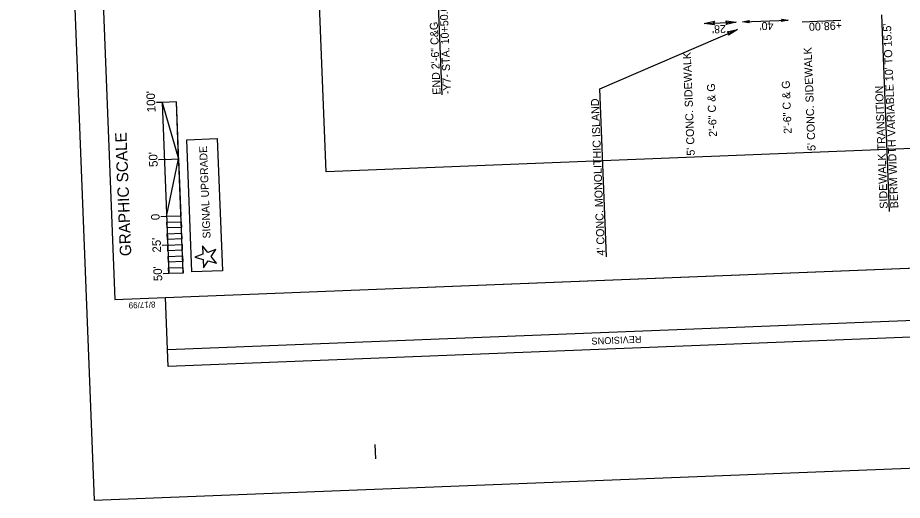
# Model space of a CAD drawing. Extents: x 1627811 to 1628977, y 762656 to 764629.
# Drawn here: x 1627811 to 1628584, y 762656 to 763078 of the extents above; entities that cross this region are included whole.
import ezdxf

# ---------------------------------------------------------------- set-up
doc = ezdxf.new("R2010")
doc.units = 0
for name, color, linetype in [('Prop Dimension', 7, 'Continuous'), ('Prop Dimension Text', 7, 'Continuous'), ('Prop DSN Text', 7, 'Continuous'), ('Prop Grid Mask', 7, 'Continuous'), ('Prop RDY Traffic Signal CELL', 7, 'Continuous'), ('Prop Terminator CELL', 7, 'Continuous'), ('Sheet Block Revision CELL', 7, 'Continuous'), ('Sheet Clip Boundary CELL', 7, 'Continuous'), ('Sheet Data Field CELL', 7, 'Continuous'), ('Sheet Plan And Profile CELL', 7, 'Continuous'), ('Sheet Plot Border Outside CELL', 7, 'Continuous'), ('Sheet Title CELL', 7, 'Continuous')]:
    doc.layers.add(name, color=color, linetype=linetype)

msp = doc.modelspace()

# ---------------------------------------------------------------- linework, layer by layer
at = {"layer": 'Prop Dimension'}
for p, q in [((1628181.73, 763010.81), (1628177.51, 763117.78)), ((1628573.2, 762908.58), (1628566.4, 763080.81)), ((1628411.15, 763073.24), (1628439.13, 763074.34)), ((1628444.62, 763074.56), (1628484.59, 763076.14)), ((1628496.92, 763074.62), (1628530.63, 763075.95)), ((1628319.92, 763015.96), (1628440.13, 763067.98)), ((1628325.72, 762868.94), (1628319.92, 763015.96))]:
    msp.add_line(p, q, dxfattribs=at)
at = {"layer": 'Prop Grid Mask'}
msp.add_lwpolyline([(1627962.94, 762855.84), (1627958.38, 762971.36), (1627985.14, 762972.42), (1627989.69, 762856.89)], close=True, dxfattribs=at)
at = {"layer": 'Prop RDY Traffic Signal CELL'}
msp.add_lwpolyline([(1627972.76, 762866.71), (1627973.05, 762859.31), (1627977.16, 762865.47), (1627984.31, 762863.46), (1627979.71, 762869.28), (1627983.83, 762875.45), (1627976.87, 762872.88), (1627972.28, 762878.7), (1627972.57, 762871.3), (1627965.61, 762868.72), (1627972.76, 762866.71)], dxfattribs=at)
at = {"layer": 'Prop Terminator CELL'}
for points in [[(1628420.2, 763072.04), (1628411.15, 763073.24), (1628420.13, 763075.19), (1628419.04, 763073.55)], [(1628430.07, 763075.54), (1628439.13, 763074.34), (1628430.15, 763072.39), (1628431.23, 763074.03)], [(1628450.5, 763073.73), (1628444.62, 763074.56), (1628450.47, 763075.78), (1628449.76, 763074.71)], [(1628478.72, 763076.97), (1628484.59, 763076.14), (1628478.74, 763074.92), (1628479.46, 763075.98)], [(1628431.25, 763065.83), (1628440.13, 763067.98), (1628432.46, 763062.92), (1628432.88, 763064.84)]]:
    msp.add_lwpolyline(points, close=True, dxfattribs=at)
at = {"layer": 'Sheet Block Revision CELL'}
msp.add_line((1628731.74, 762818.75), (1627941.71, 762787.59), dxfattribs=at)
msp.add_lwpolyline([(1628732.32, 762804.21), (1627942.28, 762773.06), (1627939.89, 762833.56), (1628729.93, 762864.71)], close=True, dxfattribs=at)
at = {"layer": 'Sheet Clip Boundary CELL'}
msp.add_lwpolyline([(1628080.25, 762943.5), (1628060.66, 763440.11), (1628567.89, 763460.11), (1628623.39, 763582.83), (1628623.86, 763610.17), (1628631.44, 763609.98), (1628639.19, 763612.32), (1628786.08, 763468.72), (1628805.66, 762972.11)], close=True, dxfattribs=at)
at = {"layer": 'Sheet Data Field CELL'}
for p, q in [((1627936.85, 763004.13), (1627931.85, 763003.94)), ((1627938.82, 762954.19), (1627933.83, 762953.99))]:
    msp.add_line(p, q, dxfattribs=at)
at = {"layer": 'Sheet Plan And Profile CELL'}
msp.add_line((1628123.76, 762692.19), (1628123.26, 762704.68), dxfattribs=at)
msp.add_lwpolyline([(1627836.47, 764330.65), (1627895.58, 762831.81), (1628944.76, 762873.18), (1628885.66, 764372.02)], close=True, dxfattribs=at)
at = {"layer": 'Sheet Plot Border Outside CELL'}
msp.add_lwpolyline([(1628976.64, 762699.3), (1628909.65, 764397.98), (1627810.51, 764354.64), (1627877.49, 762655.96)], close=True, dxfattribs=at)
at = {"layer": 'Sheet Title CELL'}
for p, q in [((1627936.85, 763004.12), (1627931.86, 763003.92)), ((1627949.35, 763004.62), (1627936.85, 763004.12)), ((1627936.85, 763004.12), (1627942.78, 762854.28)), ((1627955.26, 762854.78), (1627949.35, 763004.62)), ((1627938.83, 762954.18), (1627933.85, 762953.98)), ((1627938.83, 762954.18), (1627951.32, 762954.67)), ((1627940.81, 762904.23), (1627935.82, 762904.03)), ((1627941.8, 762879.26), (1627936.79, 762879.06)), ((1627942.78, 762854.28), (1627937.79, 762854.09))]:
    msp.add_line(p, q, dxfattribs=at)
for points in [[(1627936.85, 763004.12), (1627951.32, 762954.67), (1627949.35, 763004.62)], [(1627940.81, 762904.23), (1627951.32, 762954.67), (1627953.3, 762904.72)], [(1627941.2, 762894.24), (1627941, 762899.23), (1627953.5, 762899.73), (1627953.68, 762894.73)], [(1627941.6, 762884.25), (1627941.39, 762889.25), (1627953.88, 762889.74), (1627954.08, 762884.74)], [(1627942, 762874.26), (1627941.8, 762879.26), (1627954.28, 762879.75), (1627954.47, 762874.75)], [(1627942.38, 762864.27), (1627942.2, 762869.27), (1627954.68, 762869.76), (1627954.88, 762864.78)], [(1627942.78, 762854.28), (1627942.58, 762859.28), (1627955.07, 762859.77), (1627955.26, 762854.78)]]:
    msp.add_lwpolyline(points, close=True, dxfattribs=at)

# ---------------------------------------------------------------- texts
at = {"layer": 'Prop Dimension Text'}
for s, rotation, p in [('-Y7- STA. 10+50.00 RT.', 92.25819, (1628189.65, 763011.35)), ('END 2\'-6" C&G', 92.25819, (1628180.48, 763010.98)), ("40'", 182.25819, (1628471.56, 763074.76)), ('+98.00', 182.25819, (1628531.44, 763074.9)), ("BERM WIDTH VARIABLE 10' TO 15.5'", 92.25819, (1628580.87, 762911.61)), ("28'", 182.25819, (1628430, 763071.91)), ('SIDEWALK TRANSITION', 92.25819, (1628571.7, 762911.25))]:
    msp.add_text(s, height=7, rotation=rotation, dxfattribs=at).set_placement(p)
at = {"layer": 'Prop DSN Text'}
for s, height, p in [("5' CONC. SIDEWALK", 7, (1628508.54, 762961.86)), ("5' CONC. SIDEWALK", 7, (1628402.88, 762957.69)), ('2\'-6" C & G', 7, (1628422.26, 762974.19)), ('2\'-6" C & G', 7, (1628487.69, 762976.77)), ("4' CONC. MONOLITHIC ISLAND", 7, (1628324.3, 762870.24)), ('SIGNAL UPGRADE', 6.8072, (1627979.26, 762885.22))]:
    msp.add_text(s, height=height, rotation=92.25819, dxfattribs=at).set_placement(p)
at = {"layer": 'Sheet Block Revision CELL'}
msp.add_text('REVISIONS', height=6, rotation=182.25819, dxfattribs=at).set_placement((1628356.04, 762799.88))
at = {"layer": 'Sheet Data Field CELL'}
for s, p in [("100'", (1627931.17, 762995.67)), ("50'", (1627933.08, 762947.79)), ("25'", (1627936.04, 762872.88)), ("50'", (1627937.03, 762847.9))]:
    msp.add_text(s, height=7.498, rotation=92.26296, dxfattribs=at).set_placement(p)
at = {"layer": 'Sheet Plan And Profile CELL'}
msp.add_text('8/17/99', height=5.25, rotation=182.25819, dxfattribs=at).set_placement((1627930.88, 762829.95))
at = {"layer": 'Sheet Title CELL'}
for s, height, p in [('GRAPHIC SCALE', 9.9967, (1627909.95, 762869.8)), ('0', 7.5, (1627934.78, 762901.24))]:
    msp.add_text(s, height=height, rotation=92.26296, dxfattribs=at).set_placement(p)

doc.saveas('drawing.dxf')
